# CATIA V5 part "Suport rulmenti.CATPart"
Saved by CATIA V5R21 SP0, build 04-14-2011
Part number: Suport rulment
Bounding box of the stored display mesh (mm): x -25.362 to 25.362, y 0 to 10, z -25.496 to 25.496
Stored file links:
  C:\Users\MIRCEA\Desktop\MOM\Mogan\model\Suport rulmenti.CATPart
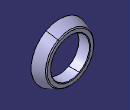
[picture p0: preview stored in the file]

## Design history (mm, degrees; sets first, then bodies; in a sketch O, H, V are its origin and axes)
Body1 (main body)
  Sketch1 on yz-plane, origin (0, 0, 0), H (0, 1, 0), V (0, 0, 1)
    axis line L1 (-29.3377, 0) -> (188.0293, 0)
    point P1 (-29.3377, 0)
    line L2 (0, 17.5) -> (10, 17.5)
    point P3 (0, 17.5)
    point P5 (0, 17.5)
    line L3 (0, 17.5) -> (0, 25.5)
    line L4 (10, 17.5) -> (10, 21.5)
    line L5 (10, 21.5) -> (0, 25.5)
    length L2 = 10
    distance P5 P3 = 0
    length L3 = 8
    length L4 = 4
    coincidence: P1 H, P3 V
    horizontal: L1 H, L2 H
    vertical: L3 V, L4 V
  Shaft1: profile Sketch1, axis Sketch1.L1, angle 360
  Chamfer1: length 0.5, angle 45, on edge [face of Shaft1 from Sketch1.L4 | face of Shaft1 from Sketch1.L2]; edge [face of Shaft1 from Sketch1.L5 | face of Shaft1 from Sketch1.L4]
